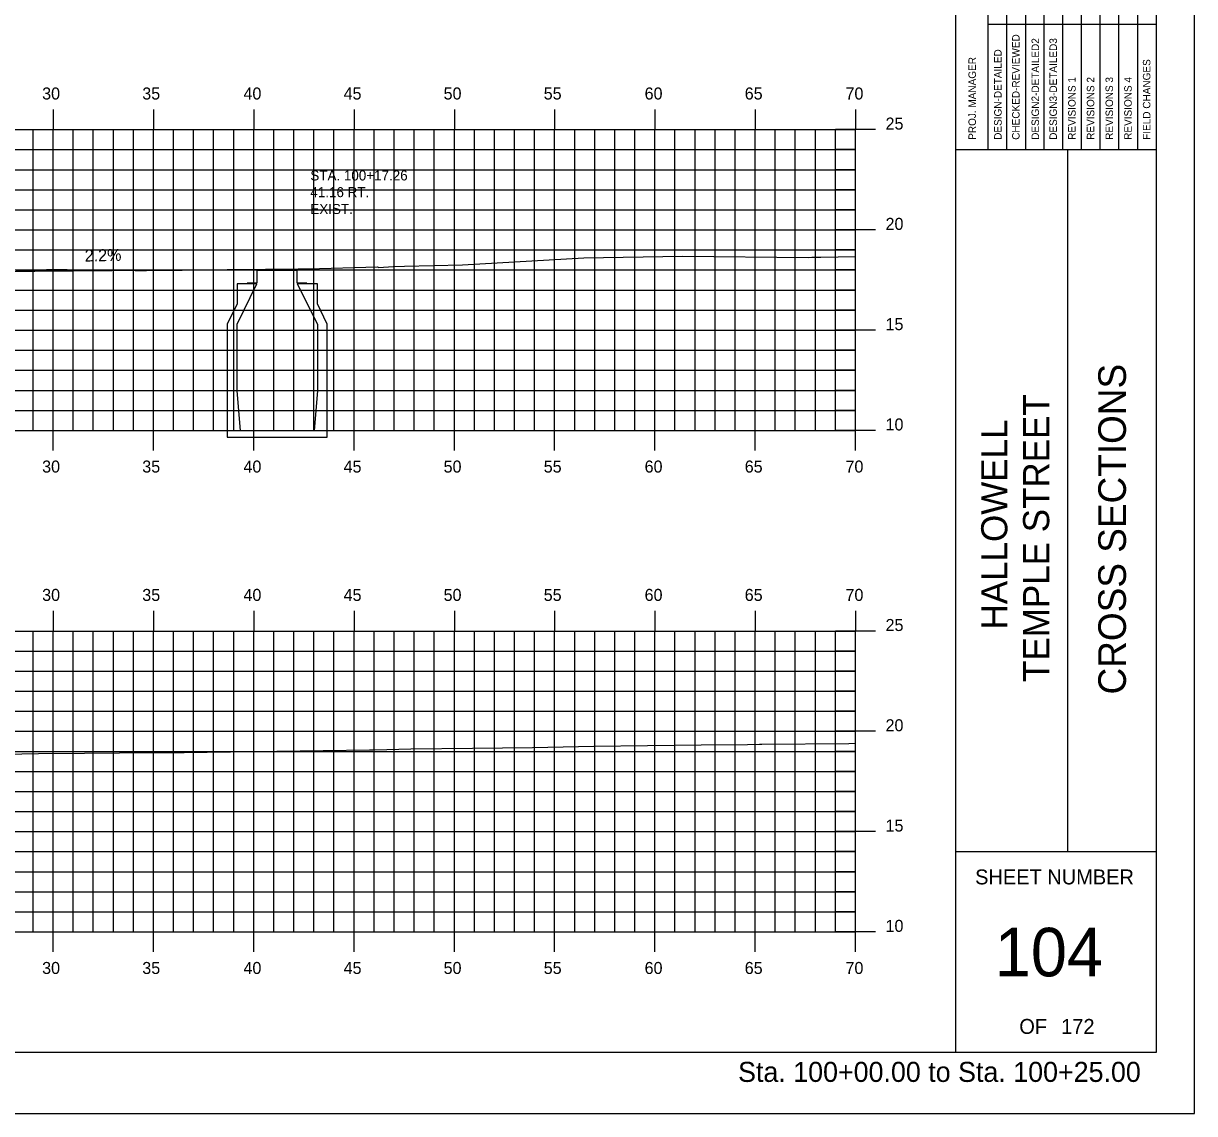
# Model space of a CAD drawing. Extents: x 1023237 to 1023407, y 394697 to 394807.
# Drawn here: x 1023348.2 to 1023406.6, y 394696.5 to 394750.9 of the extents above; entities that cross this region are included whole.
import ezdxf

# ---------------------------------------------------------------- set-up
doc = ezdxf.new("R2010")
doc.units = 0
for name, color, linetype in [('ANNOTATION', 7, 'Continuous'), ('BORDER', 7, 'Continuous'), ('D_Roadway_SlopeLines', 7, 'Continuous'), ('D_Text_Monospaced', 7, 'Continuous'), ('H_V ANNOTATION', 7, 'Continuous'), ('HIGHWAY_TITLE', 7, 'Continuous'), ('MAJOR', 7, 'Continuous'), ('MINOR', 7, 'Continuous'), ('PLOT BOUNDARY', 7, 'Continuous'), ('S_Drainage_CB', 7, 'Continuous'), ('S_Roadway_Centerline', 7, 'Continuous')]:
    doc.layers.add(name, color=color, linetype=linetype)

msp = doc.modelspace()

# ---------------------------------------------------------------- linework, layer by layer
at = {"layer": 'BORDER'}
for p, q in [((1023394.664, 394699.607), (1023394.664, 394804.61)), ((1023404.664, 394699.607), (1023404.664, 394804.607)), ((1023394.664, 394744.61), (1023404.664, 394744.61)), ((1023400.255, 394709.61), (1023400.255, 394744.61)), ((1023394.664, 394709.61), (1023404.664, 394709.61)), ((1023244.664, 394699.607), (1023404.664, 394699.607))]:
    msp.add_line(p, q, dxfattribs=at)
for points in [[(1023397.211, 394744.613), (1023397.211, 394762.11)], [(1023398.143, 394762.11), (1023398.143, 394744.613)], [(1023399.074, 394744.613), (1023399.074, 394762.11)], [(1023400.006, 394744.613), (1023400.006, 394762.11)], [(1023400.938, 394744.613), (1023400.938, 394762.11)], [(1023401.869, 394744.613), (1023401.869, 394762.11)], [(1023402.801, 394744.613), (1023402.801, 394762.11)], [(1023403.733, 394744.613), (1023403.733, 394762.11)], [(1023396.279, 394744.613), (1023396.279, 394761.404)], [(1023396.278, 394750.86), (1023404.664, 394750.86)]]:
    msp.add_lwpolyline(points, dxfattribs=at)
at = {"layer": 'D_Roadway_SlopeLines'}
msp.add_lwpolyline([(1023339.163, 394738.464), (1023362.163, 394738.659)], dxfattribs=at)
at = {"layer": 'MAJOR'}
for p, q in [((1023349.663, 394746.609), (1023349.663, 394745.607)), ((1023354.663, 394746.609), (1023354.663, 394745.607)), ((1023359.663, 394746.609), (1023359.663, 394745.607)), ((1023364.663, 394746.609), (1023364.663, 394745.607)), ((1023369.663, 394746.609), (1023369.663, 394745.607)), ((1023374.663, 394746.609), (1023374.663, 394745.607)), ((1023379.663, 394746.609), (1023379.663, 394745.607)), ((1023384.663, 394746.609), (1023384.663, 394745.607)), ((1023389.663, 394746.609), (1023389.663, 394745.607)), ((1023249.663, 394745.607), (1023389.663, 394745.607)), ((1023349.663, 394730.607), (1023349.663, 394745.607)), ((1023354.663, 394730.607), (1023354.663, 394745.607)), ((1023359.663, 394730.607), (1023359.663, 394745.607)), ((1023364.663, 394730.607), (1023364.663, 394745.607)), ((1023369.663, 394730.607), (1023369.663, 394745.607)), ((1023374.663, 394730.607), (1023374.663, 394745.607)), ((1023379.663, 394730.607), (1023379.663, 394745.607)), ((1023384.663, 394730.607), (1023384.663, 394745.607)), ((1023390.665, 394745.607), (1023388.661, 394745.607)), ((1023389.663, 394730.607), (1023389.663, 394745.607)), ((1023249.663, 394740.607), (1023389.663, 394740.607)), ((1023390.665, 394740.607), (1023388.661, 394740.607)), ((1023249.663, 394735.607), (1023389.663, 394735.607)), ((1023390.665, 394735.607), (1023388.661, 394735.607)), ((1023249.663, 394730.607), (1023389.663, 394730.607)), ((1023349.663, 394729.605), (1023349.663, 394730.607)), ((1023354.663, 394729.605), (1023354.663, 394730.607)), ((1023359.663, 394729.605), (1023359.663, 394730.607)), ((1023364.663, 394729.605), (1023364.663, 394730.607)), ((1023369.663, 394729.605), (1023369.663, 394730.607)), ((1023374.663, 394729.605), (1023374.663, 394730.607)), ((1023379.663, 394729.605), (1023379.663, 394730.607)), ((1023384.663, 394729.605), (1023384.663, 394730.607)), ((1023390.665, 394730.607), (1023388.661, 394730.607)), ((1023389.663, 394729.605), (1023389.663, 394730.607)), ((1023349.663, 394721.609), (1023349.663, 394720.607)), ((1023354.663, 394721.609), (1023354.663, 394720.607)), ((1023359.663, 394721.609), (1023359.663, 394720.607)), ((1023364.663, 394721.609), (1023364.663, 394720.607)), ((1023369.663, 394721.609), (1023369.663, 394720.607)), ((1023374.663, 394721.609), (1023374.663, 394720.607)), ((1023379.663, 394721.609), (1023379.663, 394720.607)), ((1023384.663, 394721.609), (1023384.663, 394720.607)), ((1023389.663, 394721.609), (1023389.663, 394720.607)), ((1023249.663, 394720.607), (1023389.663, 394720.607)), ((1023349.663, 394705.607), (1023349.663, 394720.607)), ((1023354.663, 394705.607), (1023354.663, 394720.607)), ((1023359.663, 394705.607), (1023359.663, 394720.607)), ((1023364.663, 394705.607), (1023364.663, 394720.607)), ((1023369.663, 394705.607), (1023369.663, 394720.607)), ((1023374.663, 394705.607), (1023374.663, 394720.607)), ((1023379.663, 394705.607), (1023379.663, 394720.607)), ((1023384.663, 394705.607), (1023384.663, 394720.607)), ((1023390.665, 394720.607), (1023388.661, 394720.607)), ((1023389.663, 394705.607), (1023389.663, 394720.607)), ((1023249.663, 394715.607), (1023389.663, 394715.607)), ((1023390.665, 394715.607), (1023388.661, 394715.607)), ((1023249.663, 394710.607), (1023389.663, 394710.607)), ((1023390.665, 394710.607), (1023388.661, 394710.607)), ((1023249.663, 394705.607), (1023389.663, 394705.607)), ((1023349.663, 394704.605), (1023349.663, 394705.607)), ((1023354.663, 394704.605), (1023354.663, 394705.607)), ((1023359.663, 394704.605), (1023359.663, 394705.607)), ((1023364.663, 394704.605), (1023364.663, 394705.607)), ((1023369.663, 394704.605), (1023369.663, 394705.607)), ((1023374.663, 394704.605), (1023374.663, 394705.607)), ((1023379.663, 394704.605), (1023379.663, 394705.607)), ((1023384.663, 394704.605), (1023384.663, 394705.607)), ((1023390.665, 394705.607), (1023388.661, 394705.607)), ((1023389.663, 394704.605), (1023389.663, 394705.607))]:
    msp.add_line(p, q, dxfattribs=at)
at = {"layer": 'MINOR'}
for p, q in [((1023348.663, 394730.607), (1023348.663, 394745.607)), ((1023350.663, 394730.607), (1023350.663, 394745.607)), ((1023351.663, 394730.607), (1023351.663, 394745.607)), ((1023352.663, 394730.607), (1023352.663, 394745.607)), ((1023353.663, 394730.607), (1023353.663, 394745.607)), ((1023355.663, 394730.607), (1023355.663, 394745.607)), ((1023356.663, 394730.607), (1023356.663, 394745.607)), ((1023357.663, 394730.607), (1023357.663, 394745.607)), ((1023358.663, 394730.607), (1023358.663, 394745.607)), ((1023360.663, 394730.607), (1023360.663, 394745.607)), ((1023361.663, 394730.607), (1023361.663, 394745.607)), ((1023362.663, 394730.607), (1023362.663, 394745.607)), ((1023363.663, 394730.607), (1023363.663, 394745.607)), ((1023365.663, 394730.607), (1023365.663, 394745.607)), ((1023366.663, 394730.607), (1023366.663, 394745.607)), ((1023367.663, 394730.607), (1023367.663, 394745.607)), ((1023368.663, 394730.607), (1023368.663, 394745.607)), ((1023370.663, 394730.607), (1023370.663, 394745.607)), ((1023371.663, 394730.607), (1023371.663, 394745.607)), ((1023372.663, 394730.607), (1023372.663, 394745.607)), ((1023373.663, 394730.607), (1023373.663, 394745.607)), ((1023375.663, 394730.607), (1023375.663, 394745.607)), ((1023376.663, 394730.607), (1023376.663, 394745.607)), ((1023377.663, 394730.607), (1023377.663, 394745.607)), ((1023378.663, 394730.607), (1023378.663, 394745.607)), ((1023380.663, 394730.607), (1023380.663, 394745.607)), ((1023381.663, 394730.607), (1023381.663, 394745.607)), ((1023382.663, 394730.607), (1023382.663, 394745.607)), ((1023383.663, 394730.607), (1023383.663, 394745.607)), ((1023385.663, 394730.607), (1023385.663, 394745.607)), ((1023386.663, 394730.607), (1023386.663, 394745.607)), ((1023387.663, 394730.607), (1023387.663, 394745.607)), ((1023388.663, 394730.607), (1023388.663, 394745.607)), ((1023249.663, 394744.607), (1023389.663, 394744.607)), ((1023389.663, 394744.607), (1023388.661, 394744.607)), ((1023249.663, 394743.607), (1023389.663, 394743.607)), ((1023389.663, 394743.607), (1023388.661, 394743.607)), ((1023249.663, 394742.607), (1023389.663, 394742.607)), ((1023389.663, 394742.607), (1023388.661, 394742.607)), ((1023249.663, 394741.607), (1023389.663, 394741.607)), ((1023389.663, 394741.607), (1023388.661, 394741.607)), ((1023249.663, 394739.607), (1023389.663, 394739.607)), ((1023389.663, 394739.607), (1023388.661, 394739.607)), ((1023249.663, 394738.607), (1023389.663, 394738.607)), ((1023389.663, 394738.607), (1023388.661, 394738.607)), ((1023249.663, 394737.607), (1023389.663, 394737.607)), ((1023389.663, 394737.607), (1023388.661, 394737.607)), ((1023249.663, 394736.607), (1023389.663, 394736.607)), ((1023389.663, 394736.607), (1023388.661, 394736.607)), ((1023249.663, 394734.607), (1023389.663, 394734.607)), ((1023389.663, 394734.607), (1023388.661, 394734.607)), ((1023249.663, 394733.607), (1023389.663, 394733.607)), ((1023389.663, 394733.607), (1023388.661, 394733.607)), ((1023249.663, 394732.607), (1023389.663, 394732.607)), ((1023389.663, 394732.607), (1023388.661, 394732.607)), ((1023249.663, 394731.607), (1023389.663, 394731.607)), ((1023389.663, 394731.607), (1023388.661, 394731.607)), ((1023348.663, 394705.607), (1023348.663, 394720.607)), ((1023350.663, 394705.607), (1023350.663, 394720.607)), ((1023351.663, 394705.607), (1023351.663, 394720.607)), ((1023352.663, 394705.607), (1023352.663, 394720.607)), ((1023353.663, 394705.607), (1023353.663, 394720.607)), ((1023355.663, 394705.607), (1023355.663, 394720.607)), ((1023356.663, 394705.607), (1023356.663, 394720.607)), ((1023357.663, 394705.607), (1023357.663, 394720.607)), ((1023358.663, 394705.607), (1023358.663, 394720.607)), ((1023360.663, 394705.607), (1023360.663, 394720.607)), ((1023361.663, 394705.607), (1023361.663, 394720.607)), ((1023362.663, 394705.607), (1023362.663, 394720.607)), ((1023363.663, 394705.607), (1023363.663, 394720.607)), ((1023365.663, 394705.607), (1023365.663, 394720.607)), ((1023366.663, 394705.607), (1023366.663, 394720.607)), ((1023367.663, 394705.607), (1023367.663, 394720.607)), ((1023368.663, 394705.607), (1023368.663, 394720.607)), ((1023370.663, 394705.607), (1023370.663, 394720.607)), ((1023371.663, 394705.607), (1023371.663, 394720.607)), ((1023372.663, 394705.607), (1023372.663, 394720.607)), ((1023373.663, 394705.607), (1023373.663, 394720.607)), ((1023375.663, 394705.607), (1023375.663, 394720.607)), ((1023376.663, 394705.607), (1023376.663, 394720.607)), ((1023377.663, 394705.607), (1023377.663, 394720.607)), ((1023378.663, 394705.607), (1023378.663, 394720.607)), ((1023380.663, 394705.607), (1023380.663, 394720.607)), ((1023381.663, 394705.607), (1023381.663, 394720.607)), ((1023382.663, 394705.607), (1023382.663, 394720.607)), ((1023383.663, 394705.607), (1023383.663, 394720.607)), ((1023385.663, 394705.607), (1023385.663, 394720.607)), ((1023386.663, 394705.607), (1023386.663, 394720.607)), ((1023387.663, 394705.607), (1023387.663, 394720.607)), ((1023388.663, 394705.607), (1023388.663, 394720.607)), ((1023249.663, 394719.607), (1023389.663, 394719.607)), ((1023389.663, 394719.607), (1023388.661, 394719.607)), ((1023249.663, 394718.607), (1023389.663, 394718.607)), ((1023389.663, 394718.607), (1023388.661, 394718.607)), ((1023249.663, 394717.607), (1023389.663, 394717.607)), ((1023389.663, 394717.607), (1023388.661, 394717.607)), ((1023249.663, 394716.607), (1023389.663, 394716.607)), ((1023389.663, 394716.607), (1023388.661, 394716.607)), ((1023249.663, 394714.607), (1023389.663, 394714.607)), ((1023389.663, 394714.607), (1023388.661, 394714.607)), ((1023249.663, 394713.607), (1023389.663, 394713.607)), ((1023389.663, 394713.607), (1023388.661, 394713.607)), ((1023249.663, 394712.607), (1023389.663, 394712.607)), ((1023389.663, 394712.607), (1023388.661, 394712.607)), ((1023249.663, 394711.607), (1023389.663, 394711.607)), ((1023389.663, 394711.607), (1023388.661, 394711.607)), ((1023249.663, 394709.607), (1023389.663, 394709.607)), ((1023389.663, 394709.607), (1023388.661, 394709.607)), ((1023249.663, 394708.607), (1023389.663, 394708.607)), ((1023389.663, 394708.607), (1023388.661, 394708.607)), ((1023249.663, 394707.607), (1023389.663, 394707.607)), ((1023389.663, 394707.607), (1023388.661, 394707.607)), ((1023249.663, 394706.607), (1023389.663, 394706.607)), ((1023389.663, 394706.607), (1023388.661, 394706.607))]:
    msp.add_line(p, q, dxfattribs=at)
at = {"layer": 'PLOT BOUNDARY'}
msp.add_lwpolyline([(1023236.57, 394696.548), (1023406.57, 394696.548), (1023406.57, 394806.548), (1023236.57, 394806.548)], close=True, dxfattribs=at)
at = {"layer": 'S_Drainage_CB'}
for p, q in [((1023359.818, 394737.909), (1023358.834, 394737.909)), ((1023358.834, 394737.909), (1023358.834, 394736.925)), ((1023358.834, 394735.908), (1023359.818, 394737.909)), ((1023362.836, 394737.909), (1023361.819, 394737.909)), ((1023361.819, 394737.909), (1023362.836, 394735.908)), ((1023362.836, 394736.925), (1023362.836, 394737.909)), ((1023358.834, 394736.925), (1023358.342, 394735.908)), ((1023363.328, 394735.908), (1023362.836, 394736.925)), ((1023358.342, 394735.908), (1023358.342, 394730.265)), ((1023358.834, 394732.594), (1023358.834, 394735.908)), ((1023362.836, 394735.908), (1023362.836, 394732.594)), ((1023363.328, 394730.265), (1023363.328, 394735.908)), ((1023358.998, 394730.593), (1023358.834, 394732.594)), ((1023362.836, 394732.594), (1023362.672, 394730.593)), ((1023358.342, 394730.265), (1023363.328, 394730.265)), ((1023362.672, 394730.593), (1023358.998, 394730.593))]:
    msp.add_line(p, q, dxfattribs=at)
msp.add_lwpolyline([(1023362.311, 394737.951), (1023361.819, 394737.951), (1023361.819, 394738.574), (1023359.818, 394738.574), (1023359.818, 394737.951), (1023359.326, 394737.951)], dxfattribs=at)
at = {"layer": 'S_Roadway_Centerline'}
for points in [[(1023347.511, 394738.538), (1023349.628, 394738.643), (1023351.099, 394738.619), (1023353.756, 394738.575), (1023353.962, 394738.575), (1023354.078, 394738.582), (1023354.307, 394738.58), (1023361.425, 394738.652), (1023361.876, 394738.657), (1023362.352, 394738.66), (1023365.833, 394738.762), (1023365.896, 394738.735), (1023366.615, 394738.786), (1023367.181, 394738.798), (1023370.068, 394738.86), (1023376.119, 394739.22), (1023381.034, 394739.29), (1023387.312, 394739.236), (1023387.483, 394739.24), (1023387.542, 394739.24), (1023387.933, 394739.243), (1023389.663, 394739.277)], [(1023347.262, 394714.469), (1023348.934, 394714.493), (1023351.229, 394714.52), (1023352.972, 394714.54), (1023354.665, 394714.554), (1023356.194, 394714.554), (1023365.433, 394714.686), (1023365.601, 394714.688), (1023366.296, 394714.705), (1023367.489, 394714.725), (1023370.561, 394714.768), (1023373.564, 394714.806), (1023375.09, 394714.832), (1023376.611, 394714.86), (1023381.976, 394714.928), (1023384.274, 394714.957), (1023384.87, 394714.965), (1023384.987, 394714.972), (1023384.997, 394714.966), (1023389.339, 394715), (1023389.663, 394715.01)]]:
    msp.add_lwpolyline(points, dxfattribs=at)

# ---------------------------------------------------------------- texts
at = {"layer": 'ANNOTATION'}
msp.add_text('2.2%', height=0.6, rotation=1.2624, dxfattribs=at).set_placement((1023351.243, 394739.025))
at = {"layer": 'BORDER'}
for s, height, rotation, p in [('CHECKED-REVIEWED', 0.37275, 90, (1023397.845, 394745.098)), ('DESIGN2-DETAILED2', 0.37275, 90, (1023398.814, 394745.098)), ('DESIGN3-DETAILED3', 0.37275, 90, (1023399.708, 394745.098)), ('DESIGN-DETAILED', 0.37275, 90, (1023396.95, 394745.098)), ('PROJ. MANAGER', 0.37275, 90, (1023395.668, 394745.098)), ('FIELD CHANGES', 0.37275, 90, (1023404.366, 394745.098)), ('REVISIONS 1', 0.37275, 90, (1023400.64, 394745.098)), ('REVISIONS 2', 0.37275, 90, (1023401.571, 394745.098)), ('REVISIONS 3', 0.37275, 90, (1023402.503, 394745.098)), ('REVISIONS 4', 0.37275, 90, (1023403.435, 394745.098)), ('CROSS SECTIONS', 1.37787, 90, (1023403.148, 394717.444)), ('SHEET NUMBER', 0.74527, 360, (1023395.629, 394707.973)), ('104', 2.4194, 360, (1023396.609, 394703.389)), ('OF', 0.7453, 360, (1023397.831, 394700.52)), ('172', 0.7453, 360, (1023399.92, 394700.52))]:
    msp.add_text(s, height=height, rotation=rotation, dxfattribs=at).set_placement(p)
at = {"layer": 'D_Text_Monospaced'}
for s, height, p in [('STA. 100+17.26', 0.49998, (1023362.485, 394743.072)), ('41.16 RT.', 0.5, (1023362.485, 394742.238)), ('EXIST. ', 0.5, (1023362.485, 394741.398))]:
    msp.add_text(s, height=height, dxfattribs=at).set_placement(p)
at = {"layer": 'H_V ANNOTATION'}
for s, height, p in [('30', 0.6, (1023349.112, 394747.107)), ('35', 0.6, (1023354.104, 394747.107)), ('40', 0.6, (1023359.15, 394747.107)), ('45', 0.6, (1023364.142, 394747.107)), ('50', 0.6, (1023369.128, 394747.107)), ('55', 0.6, (1023374.12, 394747.107)), ('60', 0.6, (1023379.15, 394747.107)), ('65', 0.6, (1023384.142, 394747.107)), ('70', 0.6, (1023389.165, 394747.107)), ('25', 0.6, (1023391.163, 394745.607)), ('20', 0.6, (1023391.163, 394740.607)), ('15', 0.6, (1023391.163, 394735.607)), ('10', 0.6, (1023391.163, 394730.607)), ('30', 0.6, (1023349.112, 394728.507)), ('35', 0.6, (1023354.104, 394728.507)), ('40', 0.6, (1023359.15, 394728.507)), ('45', 0.6, (1023364.142, 394728.507)), ('50', 0.6, (1023369.128, 394728.507)), ('55', 0.6, (1023374.12, 394728.507)), ('60', 0.6, (1023379.15, 394728.507)), ('65', 0.6, (1023384.142, 394728.507)), ('70', 0.6, (1023389.165, 394728.507)), ('30', 0.6, (1023349.112, 394722.107)), ('35', 0.6, (1023354.104, 394722.107)), ('40', 0.6, (1023359.15, 394722.107)), ('45', 0.6, (1023364.142, 394722.107)), ('50', 0.6, (1023369.128, 394722.107)), ('55', 0.6, (1023374.12, 394722.107)), ('60', 0.6, (1023379.15, 394722.107)), ('65', 0.6, (1023384.142, 394722.107)), ('70', 0.6, (1023389.165, 394722.107)), ('25', 0.6, (1023391.163, 394720.607)), ('20', 0.6, (1023391.163, 394715.607)), ('15', 0.6, (1023391.163, 394710.607)), ('10', 0.6, (1023391.163, 394705.607)), ('30', 0.6, (1023349.112, 394703.507)), ('35', 0.6, (1023354.104, 394703.507)), ('40', 0.6, (1023359.15, 394703.507)), ('45', 0.6, (1023364.142, 394703.507)), ('50', 0.6, (1023369.128, 394703.507)), ('55', 0.6, (1023374.12, 394703.507)), ('60', 0.6, (1023379.15, 394703.507)), ('65', 0.6, (1023384.142, 394703.507)), ('70', 0.6, (1023389.165, 394703.507)), ('Sta. 100+00.00 to Sta. 100+25.00', 1.0002, (1023383.809, 394698.126))]:
    msp.add_text(s, height=height, dxfattribs=at).set_placement(p)
at = {"layer": 'HIGHWAY_TITLE'}
for s, height, p in [('TEMPLE STREET', 1.30428, (1023399.323, 394718.067)), ('HALLOWELL', 1.3043, (1023397.236, 394720.684))]:
    msp.add_text(s, height=height, rotation=90, dxfattribs=at).set_placement(p)

doc.saveas('drawing.dxf')
